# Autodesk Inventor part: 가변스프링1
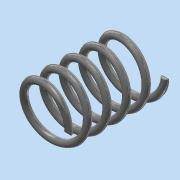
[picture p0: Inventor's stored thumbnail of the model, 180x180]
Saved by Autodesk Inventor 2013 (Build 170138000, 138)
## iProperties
Created: 2018-10
Part Number: 가변스프링1
Material: 스테인리스강
Document SubType Name: Modeling
Designer: Administrator
Density: 8.08 g/cm^3
Mass: 6.28631 g
Surface Area: 15.7888 cm^2
Volume: 0.778009 cm^3
Author: Administrator
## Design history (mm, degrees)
sketch "스케치1"
  geometry: L1 (0, 0)-(0, 28.505); L2 (0, 0)-(8, 0); L3 (0, 28.505)-(8, 28.505); C1 r 1 at (8, 0); 1 further point
  constraints: 6 end point, 2 coincident, 1 centre point, 1 parallel, 1 perpendicular, 1 vertical
  dimensions: "d0" = 28.50464 distance of L1.start L1.end (derived); "d1" = 8 distance of L1.start L2.end; "d2" = 8 distance of L1.end L3.end; "d3" = 2 diameter of C1
feature "코일1" sketch "스케치1" pitch "d4" = 10; turns "d6" = 5; dims "d5" = 28.50464 (= d0), "d7" = 0, angle "d8" = 90 deg, angle "d9" = 90 deg, "d10" = 0, "d11" = 0
sketch "스케치2"
  geometry: L1 (28.505, 12.5)-(0, 12.5); L2 (0, 12.5)-(0, -12.5); L3 (0, -12.5)-(28.505, -12.5); L4 (28.505, -12.5)-(28.505, 12.5); 2 further points
  constraints: 8 end point, 2 parallel, 1 coincident, 1 horizontal, 1 midpoint, 1 perpendicular
  dimensions: "d12" = 25 distance of L3.end L1.start; "d14" = 28.50464 distance of L2.end L3.end (derived)
extrude "돌출1" sketch "스케치2" stored distance "d15" = 20; taper "d16" = 0 deg
node "솔리드1"
